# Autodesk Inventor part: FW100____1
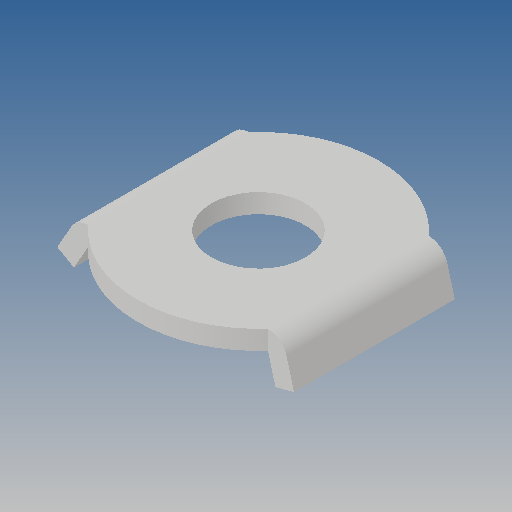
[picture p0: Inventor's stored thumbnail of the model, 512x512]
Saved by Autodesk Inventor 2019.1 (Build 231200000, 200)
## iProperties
Created: 2012-09
Part Number: FW100____1
Material: Ogólny
Document SubType Name: Modeling
Designer: CADENGINEERING4
Density: 1 g/cm^3
Appearance: Domyślna
Author: CADENGINEERING4
Revision Number: ÈÎºÎ
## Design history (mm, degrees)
feature "NONE"
node "Bryła1"
